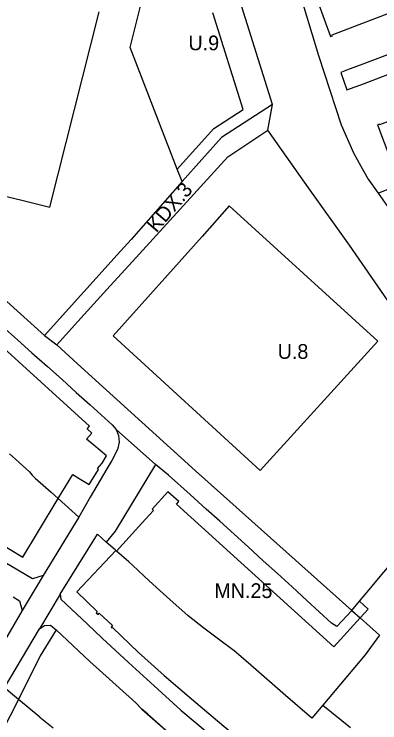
# Model space of a CAD drawing. Extents: x 7425067 to 7426806, y 5549054 to 5550619.
# Drawn here: x 7426010.9 to 7426134.9, y 5549894.6 to 5550135 of the extents above; entities that cross this region are included whole.
import ezdxf

# ---------------------------------------------------------------- set-up
doc = ezdxf.new("R2010")
doc.units = 0
for name, color, linetype in [('LIN_Linia Zabudowy Nieprzekraczalna', 7, 'Continuous'), ('LIN_linia zabudowy obowiązująca', 7, 'Continuous'), ('LIN_linie_rozgraniczajace', 7, 'Continuous'), ('TXT_Oznaczenia_przeznaczen', 7, 'Continuous')]:
    doc.layers.add(name, color=color, linetype=linetype)

msp = doc.modelspace()

# ---------------------------------------------------------------- linework, layer by layer
at = {"layer": 'LIN_Linia Zabudowy Nieprzekraczalna'}
for points in [[(7426023.0148, 5550069.5471), (7426039.6759, 5550135.8352)], [(7426088.5093, 5550102.669), (7426078.2794, 5550135.478)], [(7426066.2162, 5550082.4315), (7426078.5972, 5550096.2469), (7426088.5093, 5550102.669)], [(7425980.542, 5550080.0607), (7426023.0148, 5550069.5471)], [(7426083.87, 5550070.01), (7426074.6, 5550059.6), (7426044.4256, 5550025.9231)], [(7426134.1929, 5550024.0702), (7426083.87, 5550070.01)], [(7426044.4256, 5550025.9231), (7426094.3761, 5549980.1867)], [(7426094.3761, 5549980.1867), (7426134.1929, 5550024.0702)], [(7426128.0014, 5549935.8561), (7426130.9843, 5549933.1885), (7426128.2471, 5549930.1877), (7426119.3151, 5549920.3958)], [(7426012.3076, 5549902.588), (7426006.73, 5549891.48), (7426000.31, 5549880.37), (7425992.85, 5549867.81), (7425985.5251, 5549854.844)]]:
    msp.add_lwpolyline(points, dxfattribs=at)
at = {"layer": 'LIN_linia zabudowy obowiązująca'}
for points in [[(7426114.75, 5550139.18), (7426114.61, 5550139.48), (7426113.88, 5550139.22), (7426118.19, 5550127.45), (7426118.83, 5550127.68), (7426118.76, 5550127.94), (7426181.12, 5550151.94), (7426176.84, 5550163.62), (7426176.01, 5550163.34), (7426176.01, 5550163.07), (7426114.75, 5550139.18)], [(7426126.54, 5550110.32), (7426129.37, 5550111.37), (7426143.52, 5550116.81), (7426141.66, 5550122.79), (7426127.37, 5550117.4), (7426124.51, 5550116.32), (7426121.65, 5550115.23), (7426123.74, 5550109.29), (7426126.54, 5550110.32)], [(7426139.37, 5550086.12), (7426200.98, 5550109.55), (7426201.08, 5550109.35), (7426201.82, 5550109.68), (7426197.28, 5550121.43), (7426196.4, 5550121.11), (7426196.46, 5550120.81), (7426134.83, 5550097.46), (7426134.76, 5550097.65), (7426134.12, 5550097.47), (7426138.7, 5550085.52), (7426139.43, 5550085.78), (7426139.37, 5550086.12)], [(7426037.21, 5549992.85), (7426035.62, 5549994.38), (7426036.39, 5549995.22), (7425995.96, 5550031.98), (7425995.21, 5550031.16), (7425992.89, 5550033.28), (7425951.14, 5550071.13)], [(7425893.9, 5550021.45), (7425920.1, 5550006.36), (7425924.87, 5550003.45), (7425942.08, 5549993.19), (7425946.76, 5549990.58), (7425980.13, 5549971.02), (7425987.76, 5549966.48), (7425995.01, 5549962.2), (7426000.79, 5549958.61), (7426013.79, 5549950.82), (7426019.11, 5549959.62), (7426025.8248, 5549970.7272), (7426030.7315, 5549978.8436)], [(7426037.21, 5549992.85), (7426035.4177, 5549990.8191)], [(7426042.23, 5549985.15), (7426037.88, 5549988.77), (7426035.4177, 5549990.8191)], [(7426030.7315, 5549978.8436), (7426032.9, 5549977.54), (7426036.36, 5549975.46), (7426039.45, 5549980.58), (7426039.11, 5549980.89), (7426040.71, 5549982.66), (7426042.23, 5549985.15)], [(7426063.06, 5549972.99), (7426057.69, 5549967.1), (7426058.19, 5549966.65), (7426054.24, 5549962.31), (7426045.6205, 5549952.8395)], [(7426119.3151, 5549920.3958), (7426065.91, 5549968.75), (7426066.73, 5549969.65), (7426063.06, 5549972.99)], [(7426045.3757, 5549953.0522), (7426032.1248, 5549939.0592)], [(7426045.6205, 5549952.8395), (7426045.3757, 5549953.0522)], [(7426032.1248, 5549939.0592), (7426039.09, 5549932.41), (7426038.69, 5549931.97), (7426039.33, 5549931.35), (7426039.76, 5549931.8), (7426044.26, 5549927.62), (7426043.79, 5549927.11), (7426044.09, 5549926.83), (7426044.26, 5549926.99), (7426053.09, 5549918.46), (7426061.82, 5549910.73), (7426071.03, 5549902.74), (7426079.84, 5549895.27), (7426089.14, 5549887.45), (7426098.08, 5549879.64), (7426107.28, 5549871.91), (7426116.5, 5549864.05), (7426123.48, 5549858.2)], [(7426025.09, 5549926.11), (7426019.71, 5549917.33), (7426012.3076, 5549902.588)], [(7426063.21, 5549891.38), (7426056.21, 5549897.61), (7426054.24, 5549899.28), (7426052.14, 5549901.35), (7426045.47, 5549907.4), (7426041, 5549911.46), (7426036.59, 5549915.45), (7426025.09, 5549926.11)]]:
    msp.add_lwpolyline(points, dxfattribs=at)
at = {"layer": 'LIN_linie_rozgraniczajace'}
for points in [[(7426050.19, 5550123.7), (7426054.6154, 5550141.409), (7426056.07, 5550147.23)], [(7426106.96, 5550144.64), (7426114.165, 5550120.985)], [(7426098.46, 5550104.35), (7426087.55, 5550139.34)], [(7426067.84, 5550078.25), (7426066.2162, 5550082.4315), (7426050.19, 5550123.7)], [(7426114.165, 5550120.985), (7426121.8394, 5550097.5048)], [(7426098.46, 5550104.35), (7426081.22, 5550093.18)], [(7426096.89, 5550095.63), (7426098.46, 5550104.35)], [(7425942.03, 5550097.4), (7426021.15, 5550025.96)], [(7426121.8394, 5550097.5048), (7426126.0485, 5550088.012)], [(7426083.34, 5550086.59), (7426096.89, 5550095.63)], [(7426110.765, 5550076.11), (7426096.89, 5550095.63)], [(7426081.22, 5550093.18), (7426067.84, 5550078.25)], [(7426134.3234, 5550074.2481), (7426177.5218, 5550091.6923)], [(7426126.0485, 5550088.012), (7426128.5245, 5550083.4984)], [(7426068.355, 5550070.145), (7426083.34, 5550086.59)], [(7426128.5245, 5550083.4984), (7426131.0005, 5550078.9849)], [(7426067.84, 5550078.25), (7426050.52, 5550058.62)], [(7426131.0005, 5550078.9849), (7426134.3234, 5550074.2481), (7426137.4798, 5550069.7486)], [(7426124.64, 5550056.59), (7426110.765, 5550076.11)], [(7426053.37, 5550053.7), (7426068.355, 5550070.145)], [(7426050.52, 5550058.62), (7426045.81, 5550053.39)], [(7426137.5, 5550038.01), (7426124.64, 5550056.59)], [(7426045.81, 5550053.39), (7426033.48, 5550039.675)], [(7426042.37, 5550041.62), (7426053.37, 5550053.7)], [(7426031.37, 5550029.54), (7426042.37, 5550041.62)], [(7426033.48, 5550039.675), (7426021.15, 5550025.96)], [(7426025.34, 5550022.79), (7426031.37, 5550029.54)], [(7426006.97, 5550029), (7426012.02, 5550024.58)], [(7426012.02, 5550024.58), (7426016.89, 5550020.12)], [(7426021.15, 5550025.96), (7426025.34, 5550022.79)], [(7426025.34, 5550022.79), (7426032.4, 5550016.42)], [(7426016.89, 5550020.12), (7426022.18, 5550015.51)], [(7426022.18, 5550015.51), (7426027.11, 5550011.04)], [(7426032.4, 5550016.42), (7426072.42, 5549980.08)], [(7426027.11, 5550011.04), (7426031.89, 5550006.65)], [(7426031.89, 5550006.65), (7426036.67, 5550002.46)], [(7426036.67, 5550002.46), (7426044.13, 5549995.74)], [(7426044.13, 5549995.74), (7426045.52, 5549994.09)], [(7426058.84, 5549982.2), (7426045.52, 5549994.09)], [(7426045.52, 5549994.09), (7426046.31, 5549992.04)], [(7426046.31, 5549992.04), (7426046.52, 5549989.81)], [(7426046.52, 5549989.81), (7426045.96, 5549987.39)], [(7426009.24, 5549985.88), (7426011.31, 5549984.11)], [(7426045.96, 5549987.39), (7426043.96, 5549983.58)], [(7426011.31, 5549984.11), (7426016.03, 5549979.77), (7426017.015, 5549978.675)], [(7426043.96, 5549983.58), (7426042.29, 5549980.82)], [(7426058.84, 5549982.2), (7426045.15, 5549959.62)], [(7426063.25, 5549978.63), (7426058.84, 5549982.2)], [(7426017.015, 5549978.675), (7426018, 5549977.58)], [(7426042.29, 5549980.82), (7426036.69, 5549971.21)], [(7426070.59, 5549972.04), (7426063.25, 5549978.63)], [(7426072.42, 5549980.08), (7426125.38, 5549932.75)], [(7426018, 5549977.58), (7426023.48, 5549972.88)], [(7426023.48, 5549972.88), (7426025.8248, 5549970.7272), (7426032.76, 5549964.36)], [(7426076.05, 5549967.11), (7426070.59, 5549972.04)], [(7426036.69, 5549971.21), (7426032.76, 5549964.36)], [(7426080.63, 5549963), (7426076.05, 5549967.11)], [(7426032.76, 5549964.36), (7426020.66, 5549944.6)], [(7426085.53, 5549958.57), (7426080.63, 5549963)], [(7426045.15, 5549959.62), (7426042.04, 5549955.95)], [(7426026.51, 5549938.26), (7426039.1, 5549958.59)], [(7426039.1, 5549958.59), (7426042.04, 5549955.95)], [(7426090.38, 5549954.15), (7426085.53, 5549958.57)], [(7426049.81, 5549949.2), (7426045.6205, 5549952.8395), (7426045.3757, 5549953.0522), (7426045.1004, 5549953.2913), (7426042.04, 5549955.95)], [(7426095.4, 5549949.61), (7426090.38, 5549954.15)], [(7426017.12, 5549943.41), (7426002.67, 5549951.9)], [(7426052.76, 5549946.57), (7426049.81, 5549949.2)], [(7426100.26, 5549945.25), (7426095.4, 5549949.61)], [(7426131.79, 5549940.345), (7426135.0602, 5549944.2197), (7426138.2, 5549947.94)], [(7426055.07, 5549944.26), (7426052.76, 5549946.57)], [(7426105.2, 5549940.74), (7426100.26, 5549945.25)], [(7426020.66, 5549944.6), (7426013.56, 5549932.67)], [(7426020.66, 5549944.6), (7426017.12, 5549943.41)], [(7426057.91, 5549941.7), (7426055.07, 5549944.26)], [(7426060.35, 5549939.53), (7426057.91, 5549941.7)], [(7426110.19, 5549936.11), (7426105.2, 5549940.74)], [(7426125.38, 5549932.75), (7426128.0014, 5549935.8561), (7426131.79, 5549940.345)], [(7426026.51, 5549938.26), (7426019.44, 5549926.55)], [(7426026.51, 5549938.26), (7426026.72, 5549936.53)], [(7426064.86, 5549935.42), (7426060.35, 5549939.53)], [(7426010.59, 5549937.36), (7426012.68, 5549935.98)], [(7426012.68, 5549935.98), (7426013.56, 5549932.67)], [(7426026.72, 5549936.53), (7426035.72, 5549928.1)], [(7426066.72, 5549933.74), (7426064.86, 5549935.42)], [(7426118.53, 5549928.47), (7426110.19, 5549936.11)], [(7426069.89, 5549930.91), (7426066.72, 5549933.74)], [(7426013.56, 5549932.67), (7426007.895, 5549923.035)], [(7426075.21, 5549926.7), (7426069.89, 5549930.91)], [(7426125.38, 5549932.75), (7426120.29, 5549927.3)], [(7426125.38, 5549932.75), (7426128.2471, 5549930.1877), (7426134.7894, 5549924.3409)], [(7426035.72, 5549928.1), (7426040.78, 5549923.36)], [(7426120.29, 5549927.3), (7426118.53, 5549928.47)], [(7426007.64, 5549906.46), (7426019.44, 5549926.55)], [(7426019.44, 5549926.55), (7426021.17, 5549927.67)], [(7426021.17, 5549927.67), (7426023.23, 5549927.71)], [(7426023.23, 5549927.71), (7426025.09, 5549926.11)], [(7426025.09, 5549926.11), (7426036.59, 5549915.45)], [(7426076.07, 5549926.03), (7426075.21, 5549926.7)], [(7426080.67, 5549922.63), (7426076.07, 5549926.03)], [(7426040.78, 5549923.36), (7426049.69, 5549915.08)], [(7426134.7894, 5549924.3409), (7426129.91, 5549917.68)], [(7426085.53, 5549919), (7426080.67, 5549922.63)], [(7426086.17, 5549918.46), (7426085.53, 5549919)], [(7426091.2, 5549914.23), (7426086.17, 5549918.46)], [(7426129.91, 5549917.68), (7426115.54, 5549900.56)], [(7426036.59, 5549915.45), (7426041, 5549911.46)], [(7426049.69, 5549915.08), (7426058.39, 5549907.14)], [(7426093.86, 5549911.85), (7426091.2, 5549914.23)], [(7426041, 5549911.46), (7426045.47, 5549907.4)], [(7426099.28, 5549907.08), (7426093.86, 5549911.85)], [(7426019.55, 5549896.58), (7426012.3076, 5549902.588), (7426007.64, 5549906.46)], [(7426045.47, 5549907.4), (7426052.14, 5549901.35)], [(7426058.39, 5549907.14), (7426067.43, 5549898.97)], [(7426102.92, 5549903.92), (7426099.28, 5549907.08)], [(7426111.9, 5549896.23), (7426102.92, 5549903.92)], [(7426052.14, 5549901.35), (7426054.24, 5549899.28)], [(7426054.24, 5549899.28), (7426063.21, 5549891.38)], [(7426115.54, 5549900.56), (7426111.9, 5549896.23)], [(7426115.54, 5549900.56), (7426124.99, 5549893.01)], [(7426067.43, 5549898.97), (7426076.45, 5549891.36)], [(7426019.55, 5549896.58), (7426024.1, 5549892.94)]]:
    msp.add_lwpolyline(points, dxfattribs=at)

# ---------------------------------------------------------------- texts
at = {"layer": 'TXT_Oznaczenia_przeznaczen'}
for s, p in [('U.9', (7426070.0066, 5550122.7537)), ('U.8', (7426100.2626, 5550018.0858)), ('MN.25', (7426078.7877, 5549936.9546))]:
    msp.add_text(s, height=5, dxfattribs=at).set_placement(p)
msp.add_text('KDX.3', height=5, rotation=49.222352, dxfattribs=at).set_placement((7426059.1198, 5550060.599))

doc.saveas('drawing.dxf')
